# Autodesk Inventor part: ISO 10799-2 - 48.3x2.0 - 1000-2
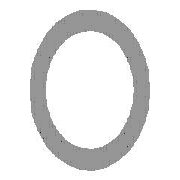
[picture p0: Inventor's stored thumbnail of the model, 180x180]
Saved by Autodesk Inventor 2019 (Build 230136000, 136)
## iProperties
IsCustomPart: 1
Created: 2018-01
Part Number: ISO 10799-2 - 48.3x2.0 - 1000-2
Material: Acier, doux
Description: Aciers de construction - Coupes creuses profilées formées à froid, soudées
Document SubType Name: Modeling
Standard: ISO
Designer: Fabian Perrée
Standard Revision: First edition 2011-09-15
Standards Organization: ISO
Language: fr-FR
Size Designation: 48.3x2.0
Categories: <MemberInstance><Categories><Category DisplayName="Profilés" InternalName="089c4875-fa83-4c05-b084-43b9cc11f5ed" Mnemonic="GRDR"><CategoryParameter DisplayName=
Stock Number: 48.3x2.0
Density: 7.85 g/cm^3
Appearance: Semi-poli
Mass: 2283.66 g
Surface Area: 2914.93 cm^2
Volume: 290.911 cm^3
_CCFamilyMember: 14
_CCFamilyDisplayName: ISO 10799-2 (Profils creux circulaires - Formés à froid) - Aciers de construction - Coupes creuses profilées formées à froid, soudées
_FrameMemberDoc: Frame Member File
_Version: 15.0.0
_GetPNFromCC: 1
G_L: 1000,000 mm
G_W: 48,300 mm
G_H: 48,300 mm
Author: Fabian Perrée
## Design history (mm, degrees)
node "Plan de départ"
node "Plan de fin"
sketch "Esquisse"
  geometry: C1 r 22.15 at (0, 0); C2 r 24.15 at (0, 0); 2 further points
  constraints: 3 coincident, 2 centre point
  dimensions: "d0" = 48.3 diameter of C2 (= G_H); "d1" = 2 radial gap between concentric circles of C2 C1 (= G_T)
extrude "Corps" new body sketch "Esquisse" stored distance "d2" = 1000 (= G_L); taper "d3" = 0 deg
node "Driven Length"
  sketch "Sketch3"
    geometry: L1 (0, 0)-(10, 0) reference
    constraints: 2 end point, 1 horizontal
  workplane "Work Plane3"
  sketch "Sketch4"
    geometry: L1 (-2, 0)-(12, 0) reference; L2 (-2, 1000)-(12, 1000) reference
    dimensions: "d7" = 1000 distance between parallel lines of L1 L2 (derived)
body "Solid1"
other parameters: "G_H" = 48.3 [user parameter; used in 1 equation term], "G_T" = 2 [user parameter; used in 1 equation term], "G_L" = 1000 (= d7) [user parameter; used in 1 equation term], "G_OFFSET_START" = 0 [user parameter; used in 1 equation term], "G_OFFSET_END" = 0 [user parameter; used in 1 equation term], "d4" = 0 (computed from G_OFFSET_START), "d6" = 90 deg, "MAS" = 0.228 [user parameter]
